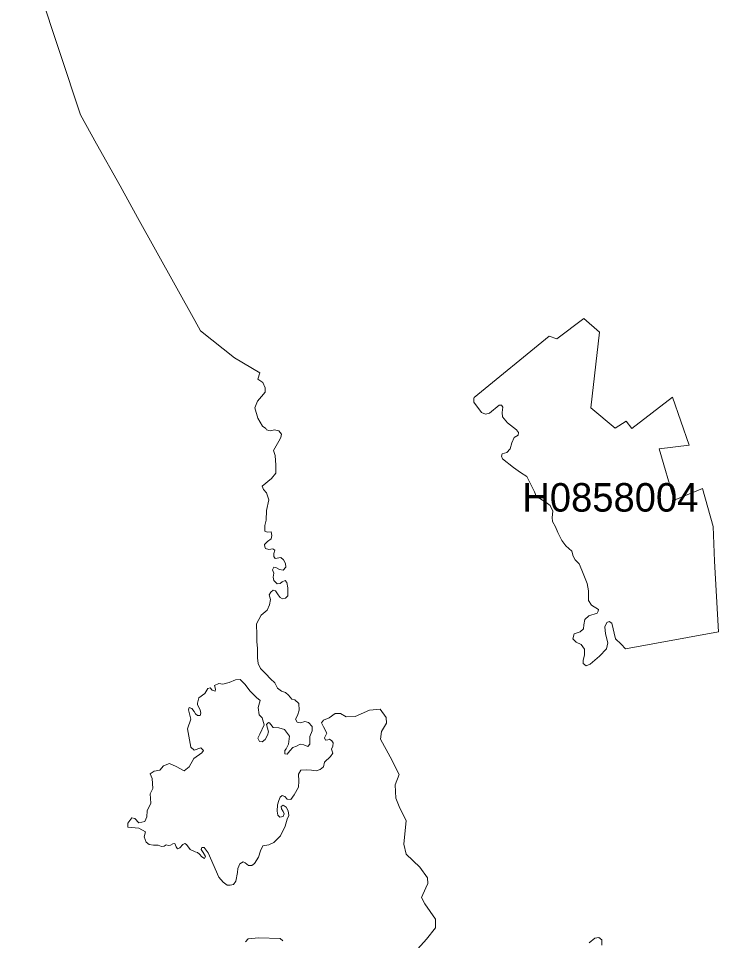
# Model space of a CAD drawing. Extents: x 369010 to 739155, y 6377141 to 6616555.
# Drawn here: x 432240 to 434694, y 6464616 to 6467848 of the extents above; entities that cross this region are included whole.
import ezdxf
from ezdxf.enums import TextEntityAlignment as Align

# ---------------------------------------------------------------- set-up
doc = ezdxf.new("R2010")
doc.units = 0
doc.header["$LTSCALE"] = 40
doc.layers.add('1', color=7, linetype='Continuous', lineweight=13)
doc.layers.add('2', color=7, linetype='Continuous')

msp = doc.modelspace()

# ---------------------------------------------------------------- linework, layer by layer
at = {"layer": '1'}
for points in [[(433085.58, 6466606.82), (432997.53, 6466659.12), (432878.53, 6466753.29), (432858.5, 6466789.7), (432657.58, 6467150.17), (432596.35, 6467261.39), (432513.26, 6467409.35), (432457.98, 6467510.64), (432240.02, 6468166.86)], [(432240.02, 6468166.86), (432457.98, 6467510.64), (432513.26, 6467409.35), (432596.35, 6467261.39), (432657.58, 6467150.17), (432858.5, 6466789.7), (432878.53, 6466753.29), (432997.53, 6466659.12), (433085.58, 6466606.82)], [(433243.96, 6465384.24), (433228.57, 6465379.94), (433216.82, 6465381.26), (433211.19, 6465392.68), (433217.65, 6465405.76), (433223.44, 6465423.63), (433222.45, 6465447.8), (433208.55, 6465459.55), (433198.12, 6465463.02), (433186.86, 6465475.93), (433175.44, 6465486.36), (433161.54, 6465490.83), (433147.97, 6465500.76), (433138.54, 6465520.12), (433123.81, 6465533.69), (433106.76, 6465551.07), (433088.06, 6465570.27), (433079.62, 6465586.99), (433077.8, 6465607.51), (433077.47, 6465624.06), (433077.47, 6465640.61), (433075.81, 6465664.28), (433075.81, 6465687.28), (433074.16, 6465726.01), (433090.21, 6465757.29), (433112.06, 6465773.84), (433119.83, 6465793.04), (433123.48, 6465812.24), (433118.51, 6465828.29), (433124.14, 6465837.89), (433133.24, 6465844.51), (433141.52, 6465842.36), (433150.29, 6465828.29), (433156.74, 6465819.19), (433165.85, 6465813.56), (433176.44, 6465816.21), (433184.71, 6465824.82), (433184.71, 6465853.12), (433181.07, 6465871.82), (433174.62, 6465877.94), (433164.52, 6465873.97), (433156.74, 6465867.85), (433146.32, 6465866.69), (433134.56, 6465878.94), (433132.25, 6465889.69), (433135.39, 6465903.76), (433130.59, 6465915.84), (433134.56, 6465925.11), (433144.99, 6465923.29), (433155.42, 6465916.84), (433168, 6465914.19), (433177.6, 6465925.11), (433175.94, 6465938.52), (433168.49, 6465950.27), (433159.39, 6465958.54), (433140.03, 6465955.73), (433134.73, 6465962.18), (433135.23, 6465973.11), (433139.2, 6465984.53), (433131.25, 6465988.83), (433117.85, 6465987.01), (433105.6, 6465990.98), (433103.45, 6465996.61), (433102.62, 6466004.55), (433112.55, 6466015.48), (433125.96, 6466024.25), (433128.28, 6466036), (433125.63, 6466048.58), (433113.21, 6466048.08), (433103.28, 6466051.56), (433103.62, 6466071.09), (433108.42, 6466089.79), (433109.57, 6466123.88), (433117.85, 6466161.12), (433109.24, 6466185.12), (433098.32, 6466196.87), (433094.35, 6466208.45), (433126.46, 6466236.09), (433141.68, 6466254.46), (433142.67, 6466282.43), (433140.19, 6466316.36), (433133.74, 6466333.74), (433152.11, 6466366.51), (433159.89, 6466379.09), (433161.71, 6466391.83), (433152.11, 6466402.59), (433136.88, 6466406.07), (433121.99, 6466402.59), (433109.41, 6466406.56), (433106.76, 6466411.36), (433095.51, 6466419.47), (433078.96, 6466447.77), (433068.53, 6466483.85), (433077.3, 6466507.35), (433091.7, 6466523.41), (433104.77, 6466538.8), (433104.28, 6466553.36), (433097, 6466572.73), (433079.12, 6466583.65), (433085.58, 6466606.82)], [(433085.58, 6466606.82), (433079.12, 6466583.65), (433097, 6466572.73), (433104.28, 6466553.36), (433104.77, 6466538.8), (433091.7, 6466523.41), (433077.3, 6466507.35), (433068.53, 6466483.85), (433078.96, 6466447.77), (433095.51, 6466419.47), (433106.76, 6466411.36), (433109.41, 6466406.56), (433121.99, 6466402.59), (433136.88, 6466406.07), (433152.11, 6466402.59), (433161.71, 6466391.83), (433159.89, 6466379.09), (433152.11, 6466366.51), (433133.74, 6466333.74), (433140.19, 6466316.36), (433142.67, 6466282.43), (433141.68, 6466254.46), (433126.46, 6466236.09), (433094.35, 6466208.45), (433098.32, 6466196.87), (433109.24, 6466185.12), (433117.85, 6466161.12), (433109.57, 6466123.88), (433108.42, 6466089.79), (433103.62, 6466071.09), (433103.28, 6466051.56), (433113.21, 6466048.08), (433125.63, 6466048.58), (433128.28, 6466036), (433125.96, 6466024.25), (433112.55, 6466015.48), (433102.62, 6466004.55), (433103.45, 6465996.61), (433105.6, 6465990.98), (433117.85, 6465987.01), (433131.25, 6465988.83), (433139.2, 6465984.53), (433135.23, 6465973.11), (433134.73, 6465962.18), (433140.03, 6465955.73), (433159.39, 6465958.54), (433168.49, 6465950.27), (433175.94, 6465938.52), (433177.6, 6465925.11), (433168, 6465914.19), (433155.42, 6465916.84), (433144.99, 6465923.29), (433134.56, 6465925.11), (433130.59, 6465915.84), (433135.39, 6465903.76), (433132.25, 6465889.69), (433134.56, 6465878.94), (433146.32, 6465866.69), (433156.74, 6465867.85), (433164.52, 6465873.97), (433174.62, 6465877.94), (433181.07, 6465871.82), (433184.71, 6465853.12), (433184.71, 6465824.82), (433176.44, 6465816.21), (433165.85, 6465813.56), (433156.74, 6465819.19), (433150.29, 6465828.29), (433141.52, 6465842.36), (433133.24, 6465844.51), (433124.14, 6465837.89), (433118.51, 6465828.29), (433123.48, 6465812.24), (433119.83, 6465793.04), (433112.06, 6465773.84), (433090.21, 6465757.29), (433074.16, 6465726.01), (433075.81, 6465687.28), (433075.81, 6465664.28), (433077.47, 6465640.61), (433077.47, 6465624.06), (433077.8, 6465607.51), (433079.62, 6465586.99), (433088.06, 6465570.27), (433106.76, 6465551.07), (433123.81, 6465533.69), (433138.54, 6465520.12), (433147.97, 6465500.76), (433161.54, 6465490.83), (433175.44, 6465486.36), (433186.86, 6465475.93), (433198.12, 6465463.02), (433208.55, 6465459.55), (433222.45, 6465447.8), (433223.44, 6465423.63), (433217.65, 6465405.76), (433211.19, 6465392.68), (433216.82, 6465381.26), (433228.57, 6465379.94), (433243.96, 6465384.24)], [(432741.49, 6464945.82), (432730.24, 6464950.62), (432713.19, 6464950.62), (432697.97, 6464952.77), (432687.21, 6464961.55), (432680.26, 6464979.59), (432685.55, 6464997.3), (432662.05, 6465010.04), (432623.65, 6465014.01), (432622.83, 6465027.91), (432637.89, 6465046.95), (432648.31, 6465044.3), (432661.39, 6465029.07), (432682.74, 6465033.87), (432689.69, 6465049.59), (432690.68, 6465071.28), (432704.09, 6465098.25), (432701.11, 6465131.02), (432710.87, 6465149.39), (432709.05, 6465184.15), (432701.61, 6465200.37), (432716.01, 6465209.97), (432735.2, 6465213.77), (432747.95, 6465228.67), (432769.79, 6465236.61), (432792.8, 6465226.19), (432820.27, 6465211.79), (432838.64, 6465225.36), (432855.19, 6465253.99), (432882.5, 6465274.51), (432888.46, 6465282.96), (432879.19, 6465292.06), (432856.19, 6465283.78), (432844.77, 6465293.71), (432832.52, 6465358.92), (432844.27, 6465392.02), (432836, 6465425.62), (432838.48, 6465433.4), (432847.25, 6465429.92), (432855.53, 6465418.67), (432861.15, 6465410.89), (432867.77, 6465405.1), (432877.37, 6465405.1), (432878.7, 6465413.87), (432876.88, 6465425.12), (432868.1, 6465442.17), (432867.28, 6465448.79), (432872.08, 6465467), (432892.93, 6465482.72), (432904.18, 6465500.1), (432911.47, 6465502.41), (432919.24, 6465494.47), (432929.67, 6465490.99), (432930.99, 6465497.61), (432927.19, 6465510.69), (432942.41, 6465516.81), (432956.81, 6465514.5), (432978.33, 6465521.45), (433000.51, 6465530.22), (433017.06, 6465531.05), (433032.95, 6465514.5), (433051.65, 6465490.17), (433074.82, 6465468.82), (433087.23, 6465457.56), (433079.62, 6465433.4), (433083.59, 6465408.08), (433093.69, 6465396.82), (433101.13, 6465372.49), (433085.58, 6465339.39), (433078.96, 6465325.99), (433084.42, 6465313.9), (433094.68, 6465312.42), (433104.61, 6465320.69), (433113.38, 6465335.92), (433116.86, 6465347.67), (433109.9, 6465373.32), (433116.86, 6465381.1), (433120.33, 6465378.95), (433124.8, 6465374.15), (433133.08, 6465363.72), (433152.44, 6465361.74), (433172.47, 6465356.11), (433190.17, 6465332.77), (433186.7, 6465304.97), (433178.92, 6465288.42), (433173.29, 6465282.79), (433173.79, 6465270.54), (433181.9, 6465269.72), (433191.5, 6465281.47), (433201.92, 6465293.55), (433214.01, 6465297.69), (433227.58, 6465304.64), (433240.65, 6465302.65), (433254.22, 6465296.2), (433260.84, 6465304.47), (433261.34, 6465331.45), (433269.78, 6465351.64), (433269.29, 6465366.7), (433256.71, 6465380.27), (433243.96, 6465384.24)], [(433243.96, 6465384.24), (433256.71, 6465380.27), (433269.29, 6465366.7), (433269.78, 6465351.64), (433261.34, 6465331.45), (433260.84, 6465304.47), (433254.22, 6465296.2), (433240.65, 6465302.65), (433227.58, 6465304.64), (433214.01, 6465297.69), (433201.92, 6465293.55), (433191.5, 6465281.47), (433181.9, 6465269.72), (433173.79, 6465270.54), (433173.29, 6465282.79), (433178.92, 6465288.42), (433186.7, 6465304.97), (433190.17, 6465332.77), (433172.47, 6465356.11), (433152.44, 6465361.74), (433133.08, 6465363.72), (433124.8, 6465374.15), (433120.33, 6465378.95), (433116.86, 6465381.1), (433109.9, 6465373.32), (433116.86, 6465347.67), (433113.38, 6465335.92), (433104.61, 6465320.69), (433094.68, 6465312.42), (433084.42, 6465313.9), (433078.96, 6465325.99), (433085.58, 6465339.39), (433101.13, 6465372.49), (433093.69, 6465396.82), (433083.59, 6465408.08), (433079.62, 6465433.4), (433087.23, 6465457.56), (433074.82, 6465468.82), (433051.65, 6465490.17), (433032.95, 6465514.5), (433017.06, 6465531.05), (433000.51, 6465530.22), (432978.33, 6465521.45), (432956.81, 6465514.5), (432942.41, 6465516.81), (432927.19, 6465510.69), (432930.99, 6465497.61), (432929.67, 6465490.99), (432919.24, 6465494.47), (432911.47, 6465502.41), (432904.18, 6465500.1), (432892.93, 6465482.72), (432872.08, 6465467), (432867.28, 6465448.79), (432868.1, 6465442.17), (432876.88, 6465425.12), (432878.7, 6465413.87), (432877.37, 6465405.1), (432867.77, 6465405.1), (432861.15, 6465410.89), (432855.53, 6465418.67), (432847.25, 6465429.92), (432838.48, 6465433.4), (432836, 6465425.62), (432844.27, 6465392.02), (432832.52, 6465358.92), (432844.77, 6465293.71), (432856.19, 6465283.78), (432879.19, 6465292.06), (432888.46, 6465282.96), (432882.5, 6465274.51), (432855.19, 6465253.99), (432838.64, 6465225.36), (432820.27, 6465211.79), (432792.8, 6465226.19), (432769.79, 6465236.61), (432747.95, 6465228.67), (432735.2, 6465213.77), (432716.01, 6465209.97), (432701.61, 6465200.37), (432709.05, 6465184.15), (432710.87, 6465149.39), (432701.11, 6465131.02), (432704.09, 6465098.25), (432690.68, 6465071.28), (432689.69, 6465049.59), (432682.74, 6465033.87), (432661.39, 6465029.07), (432648.31, 6465044.3), (432637.89, 6465046.95), (432622.83, 6465027.91), (432623.65, 6465014.01), (432662.05, 6465010.04), (432685.55, 6464997.3), (432680.26, 6464979.59), (432687.21, 6464961.55), (432697.97, 6464952.77), (432713.19, 6464950.62), (432730.24, 6464950.62), (432741.49, 6464945.82)], [(433529.62, 6465377.95), (433528.3, 6465397.65), (433507.94, 6465427.77), (433470.54, 6465424.13), (433420.39, 6465401.95), (433388.61, 6465400.63), (433369.08, 6465412.38), (433350.38, 6465412.71), (433329.2, 6465396.49), (433309.17, 6465388.71), (433302.22, 6465379.61), (433309.5, 6465366.04), (433320.92, 6465343.86), (433312.98, 6465326.48), (433315.79, 6465318.7), (433324.07, 6465319.53), (433329.69, 6465321.68), (433337.97, 6465316.06), (433343.27, 6465309.11), (433341.44, 6465297.35), (433337.14, 6465287.76), (433341.94, 6465272.86), (433334.16, 6465261.61), (433312.48, 6465241.74), (433308.67, 6465225.19), (433297.75, 6465215.6), (433283.35, 6465210.8), (433266.8, 6465213.77), (433248.43, 6465215.1), (433230.23, 6465213.11), (433221.45, 6465199.21), (433222.78, 6465175.54), (433221.95, 6465154.19), (433206.23, 6465127.22), (433194.15, 6465111.16), (433181.57, 6465112.49), (433173.29, 6465121.26), (433164.52, 6465124.24), (433156.74, 6465119.11), (433152.27, 6465107.36), (433148.47, 6465091.96), (433147.14, 6465069.79), (433148.8, 6465055.39), (433155.75, 6465049.1), (433168, 6465050.75), (433170.98, 6465060.85), (433168, 6465069.12), (433161.54, 6465077.73), (433161.05, 6465086.5), (433168, 6465090.47), (433178.09, 6465083.52), (433185.37, 6465070.78), (433187.2, 6465054.73), (433182.4, 6465041.65), (433174.95, 6465016.82), (433158.73, 6464983.89), (433135.23, 6464959.89), (433117.35, 6464952.11), (433096, 6464948.64), (433088.06, 6464930.76), (433081.6, 6464908.42), (433066.87, 6464886.74), (433057.77, 6464878.96), (433046.35, 6464878.96), (433034.27, 6464888.39), (433027.65, 6464891.87), (433015.4, 6464884.92), (433009.44, 6464868.86), (433007.62, 6464855.29), (433001.67, 6464824.34), (432993.39, 6464813.42), (432982.47, 6464810.44), (432971.05, 6464810.44), (432957.64, 6464820.87), (432942.41, 6464839.07), (432904.85, 6464924.31), (432890.61, 6464943.01), (432883.16, 6464942.18), (432880.85, 6464935.56), (432887.47, 6464924.8), (432895.25, 6464910.74), (432892.27, 6464904.28), (432882.67, 6464909.91), (432874.89, 6464918.68), (432867.77, 6464924.8), (432859.17, 6464927.78), (432841.79, 6464935.23), (432828.71, 6464952.61), (432823.42, 6464956.58), (432816.47, 6464953.44), (432805.87, 6464940.86), (432797.93, 6464937.38), (432792.8, 6464944.33), (432788, 6464957.08), (432780.72, 6464955.42), (432772.94, 6464950.62), (432765.49, 6464949.8), (432757.71, 6464951.95), (432750.26, 6464947.48), (432741.49, 6464945.82)], [(432741.49, 6464945.82), (432750.26, 6464947.48), (432757.71, 6464951.95), (432765.49, 6464949.8), (432772.94, 6464950.62), (432780.72, 6464955.42), (432788, 6464957.08), (432792.8, 6464944.33), (432797.93, 6464937.38), (432805.87, 6464940.86), (432816.47, 6464953.44), (432823.42, 6464956.58), (432828.71, 6464952.61), (432841.79, 6464935.23), (432859.17, 6464927.78), (432867.77, 6464924.8), (432874.89, 6464918.68), (432882.67, 6464909.91), (432892.27, 6464904.28), (432895.25, 6464910.74), (432887.47, 6464924.8), (432880.85, 6464935.56), (432883.16, 6464942.18), (432890.61, 6464943.01), (432904.85, 6464924.31), (432942.41, 6464839.07), (432957.64, 6464820.87), (432971.05, 6464810.44), (432982.47, 6464810.44), (432993.39, 6464813.42), (433001.67, 6464824.34), (433007.62, 6464855.29), (433009.44, 6464868.86), (433015.4, 6464884.92), (433027.65, 6464891.87), (433034.27, 6464888.39), (433046.35, 6464878.96), (433057.77, 6464878.96), (433066.87, 6464886.74), (433081.6, 6464908.42), (433088.06, 6464930.76), (433096, 6464948.64), (433117.35, 6464952.11), (433135.23, 6464959.89), (433158.73, 6464983.89), (433174.95, 6465016.82), (433182.4, 6465041.65), (433187.2, 6465054.73), (433185.37, 6465070.78), (433178.09, 6465083.52), (433168, 6465090.47), (433161.05, 6465086.5), (433161.54, 6465077.73), (433168, 6465069.12), (433170.98, 6465060.85), (433168, 6465050.75), (433155.75, 6465049.1), (433148.8, 6465055.39), (433147.14, 6465069.79), (433148.47, 6465091.96), (433152.27, 6465107.36), (433156.74, 6465119.11), (433164.52, 6465124.24), (433173.29, 6465121.26), (433181.57, 6465112.49), (433194.15, 6465111.16), (433206.23, 6465127.22), (433221.95, 6465154.19), (433222.78, 6465175.54), (433221.45, 6465199.21), (433230.23, 6465213.11), (433248.43, 6465215.1), (433266.8, 6465213.77), (433283.35, 6465210.8), (433297.75, 6465215.6), (433308.67, 6465225.19), (433312.48, 6465241.74), (433334.16, 6465261.61), (433341.94, 6465272.86), (433337.14, 6465287.76), (433341.44, 6465297.35), (433343.27, 6465309.11), (433337.97, 6465316.06), (433329.69, 6465321.68), (433324.07, 6465319.53), (433315.79, 6465318.7), (433312.98, 6465326.48), (433320.92, 6465343.86), (433309.5, 6465366.04), (433302.22, 6465379.61), (433309.17, 6465388.71), (433329.2, 6465396.49), (433350.38, 6465412.71), (433369.08, 6465412.38), (433388.61, 6465400.63), (433420.39, 6465401.95), (433470.54, 6465424.13), (433507.94, 6465427.77), (433528.3, 6465397.65), (433529.62, 6465377.95)], [(433639.35, 6464587.18), (433670.63, 6464621.6), (433701.25, 6464661.16), (433702.24, 6464691.11), (433664.18, 6464745.23), (433652.92, 6464767.24), (433667.65, 6464801.17), (433674.94, 6464816.9), (433673.94, 6464836.43), (433646.63, 6464874), (433598.47, 6464919.34), (433590.69, 6464954.26), (433599.3, 6465037.35), (433576.79, 6465080.38), (433562.56, 6465115.63), (433560.57, 6465161.64), (433574.14, 6465198.22), (433542.7, 6465260.12), (433508.77, 6465322.68), (433512.58, 6465349.65), (433529.62, 6465377.95)], [(433529.62, 6465377.95), (433512.58, 6465349.65), (433508.77, 6465322.68), (433542.7, 6465260.12), (433574.14, 6465198.22), (433560.57, 6465161.64), (433562.56, 6465115.63), (433576.79, 6465080.38), (433599.3, 6465037.35), (433590.69, 6464954.26), (433598.47, 6464919.34), (433646.63, 6464874), (433673.94, 6464836.43), (433674.94, 6464816.9), (433667.65, 6464801.17), (433652.92, 6464767.24), (433664.18, 6464745.23), (433702.24, 6464691.11), (433701.25, 6464661.16), (433670.63, 6464621.6), (433639.35, 6464587.18)], [(434239.8, 6464608.86), (434259.83, 6464624.25), (434274.72, 6464626.73), (434284.16, 6464619.45), (434284.49, 6464600.58)], [(433035.92, 6464611.51), (433045.19, 6464622.26), (433081.77, 6464625.74), (433157.74, 6464623.09), (433166.51, 6464615.48)]]:
    msp.add_lwpolyline(points, dxfattribs=at)
for points in [[(433837.13, 6466519.77), (433836.3, 6466517.28), (433836.3, 6466503.38), (433862.78, 6466467.8), (433876.68, 6466460.85), (433890.59, 6466464.32), (433925.18, 6466493.29), (433933.29, 6466493.29), (433937.76, 6466486.33), (433935.44, 6466467.8), (433936.76, 6466451.74), (433953.98, 6466430.89), (433985.09, 6466406.73), (433993.2, 6466397.46), (433990.88, 6466388.19), (433976.98, 6466380.08), (433969.04, 6466360.55), (433963.24, 6466339.7), (433951.66, 6466326.95), (433935.44, 6466322.32), (433933.29, 6466314.38), (433936.76, 6466305.11), (433974.83, 6466274.99), (434000.15, 6466256.62), (434021.34, 6466243.38), (434049.14, 6466189.09), (434054.77, 6466174.19), (434089.36, 6466152.18), (434103.26, 6466141.76), (434112.53, 6466121.07), (434110.21, 6466099.06), (434111.37, 6466085.32), (434121.8, 6466066.78), (434129.91, 6466047.09), (434144.8, 6466018.46), (434158.7, 6466000.08), (434179.39, 6465981.55), (434184.03, 6465964.17), (434190.98, 6465950.43), (434204.88, 6465936.53), (434215.14, 6465914.52), (434233.68, 6465868.34), (434238.31, 6465841.86), (434238.31, 6465808.43), (434248.74, 6465792.21), (434272.9, 6465777.15), (434271.74, 6465770.36), (434268.27, 6465763.41), (434239.47, 6465754.15), (434225.57, 6465741.4), (434222.09, 6465722.87), (434220.93, 6465709.29), (434208.35, 6465698.87), (434187.5, 6465690.92), (434182.87, 6465673.54), (434194.45, 6465661.96), (434211.83, 6465653.85), (434224.41, 6465637.8), (434224.41, 6465616.94), (434219.77, 6465599.56), (434219.77, 6465586.99), (434230.2, 6465578.88), (434244.1, 6465584.67), (434276.38, 6465613.47), (434300.54, 6465638.95), (434305.17, 6465659.64), (434297.23, 6465690.92), (434294.91, 6465716.24), (434301.7, 6465731.31), (434310.97, 6465734.78), (434320.24, 6465728.99), (434332.98, 6465673.54), (434352.51, 6465655.01), (434367.07, 6465638.62), (434693.78, 6465698.7), (434679.71, 6465946.3), (434674.41, 6466068.11), (434637.18, 6466200.68), (434538.2, 6466159.63), (434485.24, 6466340.03), (434591.33, 6466352.44), (434532.91, 6466520.43), (434389.75, 6466410.87), (434370.38, 6466437.35), (434331.49, 6466412.52), (434246.59, 6466483.36), (434276.71, 6466748.49), (434221.93, 6466796.32), (434126.43, 6466725.65), (434099.95, 6466734.43)], [(434367.07, 6465638.62), (434352.51, 6465655.01), (434332.98, 6465673.54), (434320.24, 6465728.99), (434310.97, 6465734.78), (434301.7, 6465731.31), (434294.91, 6465716.24), (434297.23, 6465690.92), (434305.17, 6465659.64), (434300.54, 6465638.95), (434276.38, 6465613.47), (434244.1, 6465584.67), (434230.2, 6465578.88), (434219.77, 6465586.99), (434219.77, 6465599.56), (434224.41, 6465616.94), (434224.41, 6465637.8), (434211.83, 6465653.85), (434194.45, 6465661.96), (434182.87, 6465673.54), (434187.5, 6465690.92), (434208.35, 6465698.87), (434220.93, 6465709.29), (434222.09, 6465722.87), (434225.57, 6465741.4), (434239.47, 6465754.15), (434268.27, 6465763.41), (434271.74, 6465770.36), (434272.9, 6465777.15), (434248.74, 6465792.21), (434238.31, 6465808.43), (434238.31, 6465841.86), (434233.68, 6465868.34), (434215.14, 6465914.52), (434204.88, 6465936.53), (434190.98, 6465950.43), (434184.03, 6465964.17), (434179.39, 6465981.55), (434158.7, 6466000.08), (434144.8, 6466018.46), (434129.91, 6466047.09), (434121.8, 6466066.78), (434111.37, 6466085.32), (434110.21, 6466099.06), (434112.53, 6466121.07), (434103.26, 6466141.76), (434089.36, 6466152.18), (434054.77, 6466174.19), (434049.14, 6466189.09), (434021.34, 6466243.38), (434000.15, 6466256.62), (433974.83, 6466274.99), (433936.76, 6466305.11), (433933.29, 6466314.38), (433935.44, 6466322.32), (433951.66, 6466326.95), (433963.24, 6466339.7), (433969.04, 6466360.55), (433976.98, 6466380.08), (433990.88, 6466388.19), (433993.2, 6466397.46), (433985.09, 6466406.73), (433953.98, 6466430.89), (433936.76, 6466451.74), (433935.44, 6466467.8), (433937.76, 6466486.33), (433933.29, 6466493.29), (433925.18, 6466493.29), (433890.59, 6466464.32), (433876.68, 6466460.85), (433862.78, 6466467.8), (433836.3, 6466503.38), (433836.3, 6466517.28), (433837.13, 6466519.77), (434099.95, 6466734.43), (434126.43, 6466725.65), (434221.93, 6466796.32), (434276.71, 6466748.49), (434246.59, 6466483.36), (434331.49, 6466412.52), (434370.38, 6466437.35), (434389.75, 6466410.87), (434532.91, 6466520.43), (434591.33, 6466352.44), (434485.24, 6466340.03), (434538.2, 6466159.63), (434637.18, 6466200.68), (434674.41, 6466068.11), (434679.71, 6465946.3), (434693.78, 6465698.7)]]:
    msp.add_lwpolyline(points, close=True, dxfattribs=at)

# ---------------------------------------------------------------- texts
at = {"layer": '2'}
msp.add_text('H0858004', height=100, dxfattribs=at).set_placement((434314.46, 6466119.8), align=Align.CENTER)

doc.saveas('drawing.dxf')
